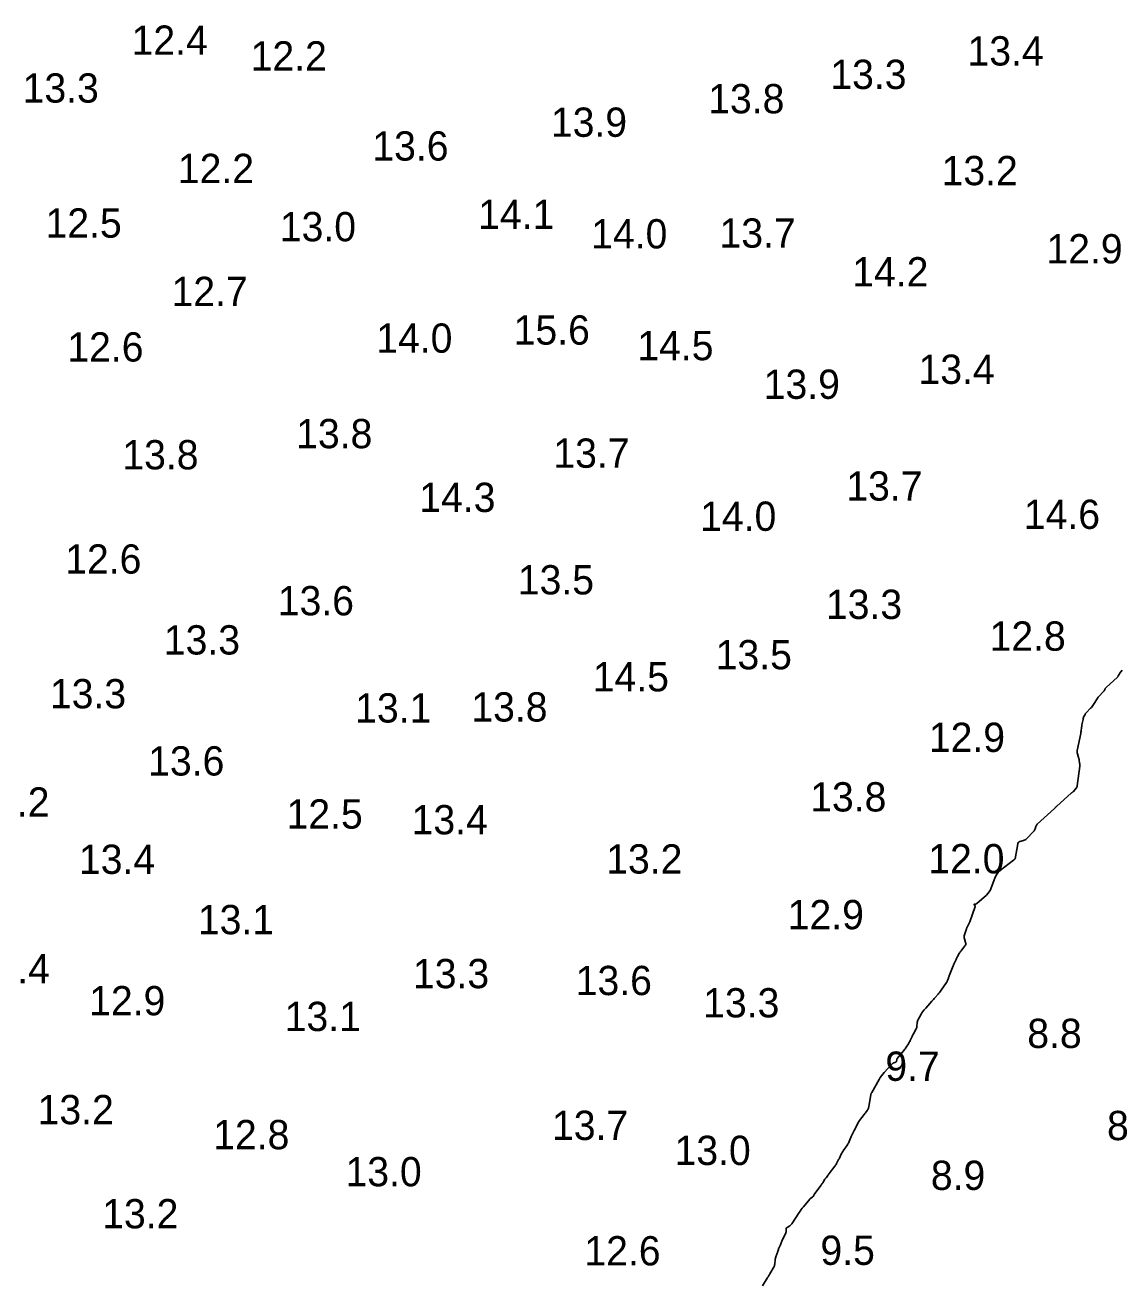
# Model space of a CAD drawing. Extents: x 815352 to 820877, y 582403 to 597439.
# Drawn here: x 820269.3 to 820456.5, y 589266 to 589480.1 of the extents above; entities that cross this region are included whole.
import ezdxf

# ---------------------------------------------------------------- set-up
doc = ezdxf.new("R2010")
doc.units = 0
doc.layers.add('V-CONT-EL12', color=7, linetype='Continuous')
doc.layers.add('V-TOPO-SOUN', color=7, linetype='Continuous')

msp = doc.modelspace()

# ---------------------------------------------------------------- linework, layer by layer
at = {"layer": 'V-CONT-EL12'}
msp.add_lwpolyline([(820395.26, 589264.81), (820396.07, 589266.1), (820396.11, 589266.16), (820396.15, 589266.22), (820396.19, 589266.29), (820396.23, 589266.35), (820396.39, 589266.6), (820396.43, 589266.66), (820396.47, 589266.73), (820396.51, 589266.79), (820396.54, 589266.86), (820397.25, 589268.13), (820397.31, 589268.25), (820397.35, 589268.38), (820397.38, 589268.51), (820397.4, 589268.65), (820397.45, 589269.2), (820397.47, 589269.34), (820397.49, 589269.47), (820397.52, 589269.6), (820397.56, 589269.74), (820397.88, 589270.66), (820397.93, 589270.81), (820397.99, 589270.96), (820398.04, 589271.11), (820398.1, 589271.25), (820398.33, 589271.84), (820398.39, 589271.98), (820398.45, 589272.13), (820398.51, 589272.27), (820398.58, 589272.42), (820399.26, 589273.87), (820399.29, 589273.94), (820399.32, 589274.03), (820399.33, 589274.11), (820399.33, 589274.2), (820399.33, 589274.54), (820399.34, 589274.62), (820399.37, 589274.69), (820399.42, 589274.75), (820399.48, 589274.8), (820399.94, 589275.07), (820400.03, 589275.14), (820400.12, 589275.21), (820400.2, 589275.3), (820400.27, 589275.39), (820401.53, 589277.32), (820401.7, 589277.58), (820401.88, 589277.83), (820402.07, 589278.07), (820402.26, 589278.31), (820403.34, 589279.63), (820403.39, 589279.68), (820403.44, 589279.73), (820403.49, 589279.77), (820403.55, 589279.81), (820403.83, 589279.97), (820403.86, 589280), (820403.89, 589280.03), (820403.92, 589280.06), (820403.94, 589280.09), (820404.03, 589280.25), (820404.05, 589280.29), (820404.07, 589280.32), (820404.1, 589280.36), (820404.12, 589280.39), (820405.23, 589281.94), (820405.32, 589282.06), (820405.4, 589282.18), (820405.49, 589282.31), (820405.57, 589282.43), (820405.95, 589283), (820406.01, 589283.09), (820406.07, 589283.17), (820406.13, 589283.26), (820406.19, 589283.34), (820406.43, 589283.66), (820406.49, 589283.75), (820406.55, 589283.83), (820406.61, 589283.91), (820406.67, 589283.99), (820407.62, 589285.22), (820407.71, 589285.33), (820407.78, 589285.44), (820407.85, 589285.56), (820407.92, 589285.68), (820408.17, 589286.15), (820408.23, 589286.27), (820408.29, 589286.4), (820408.36, 589286.52), (820408.42, 589286.64), (820408.74, 589287.3), (820408.82, 589287.45), (820408.9, 589287.59), (820408.99, 589287.73), (820409.08, 589287.87), (820409.8, 589288.91), (820409.88, 589289.04), (820409.96, 589289.17), (820410.03, 589289.3), (820410.09, 589289.44), (820410.31, 589290.01), (820410.37, 589290.15), (820410.43, 589290.29), (820410.49, 589290.42), (820410.56, 589290.56), (820410.87, 589291.2), (820410.95, 589291.35), (820411.03, 589291.5), (820411.1, 589291.65), (820411.18, 589291.8), (820411.5, 589292.43), (820411.58, 589292.59), (820411.67, 589292.74), (820411.76, 589292.88), (820411.86, 589293.02), (820412.65, 589294.06), (820412.71, 589294.14), (820412.77, 589294.22), (820412.83, 589294.29), (820412.88, 589294.37), (820413.15, 589294.74), (820413.18, 589294.79), (820413.21, 589294.84), (820413.24, 589294.89), (820413.27, 589294.94), (820413.37, 589295.16), (820413.4, 589295.22), (820413.41, 589295.27), (820413.43, 589295.33), (820413.44, 589295.39), (820413.76, 589297.49), (820413.76, 589297.53), (820413.77, 589297.56), (820413.79, 589297.59), (820413.81, 589297.61), (820413.88, 589297.73), (820413.9, 589297.75), (820413.92, 589297.78), (820413.94, 589297.81), (820413.96, 589297.84), (820415.21, 589300.07), (820415.4, 589300.38), (820415.6, 589300.69), (820415.83, 589300.97), (820416.07, 589301.25), (820417.47, 589302.76), (820417.52, 589302.81), (820417.58, 589302.85), (820417.64, 589302.88), (820417.71, 589302.91), (820418.03, 589303), (820418.08, 589303.02), (820418.12, 589303.05), (820418.15, 589303.1), (820418.17, 589303.15), (820418.21, 589303.4), (820418.22, 589303.46), (820418.24, 589303.52), (820418.27, 589303.57), (820418.3, 589303.62), (820419.44, 589305.03), (820419.55, 589305.16), (820419.65, 589305.3), (820419.74, 589305.43), (820419.83, 589305.57), (820420.2, 589306.15), (820420.28, 589306.28), (820420.36, 589306.42), (820420.44, 589306.56), (820420.51, 589306.7), (820420.77, 589307.27), (820420.84, 589307.41), (820420.91, 589307.56), (820420.98, 589307.7), (820421.06, 589307.84), (820421.54, 589308.73), (820421.59, 589308.84), (820421.63, 589308.95), (820421.65, 589309.07), (820421.67, 589309.19), (820421.69, 589309.69), (820421.7, 589309.81), (820421.73, 589309.93), (820421.77, 589310.05), (820421.82, 589310.16), (820422.4, 589311.22), (820422.45, 589311.31), (820422.51, 589311.41), (820422.57, 589311.5), (820422.64, 589311.58), (820422.91, 589311.92), (820422.98, 589312), (820423.05, 589312.09), (820423.13, 589312.17), (820423.2, 589312.25), (820424.22, 589313.41), (820424.36, 589313.57), (820424.49, 589313.72), (820424.63, 589313.88), (820424.76, 589314.03), (820425.29, 589314.65), (820425.42, 589314.81), (820425.55, 589314.97), (820425.67, 589315.13), (820425.79, 589315.3), (820426.69, 589316.61), (820426.75, 589316.7), (820426.8, 589316.79), (820426.85, 589316.88), (820426.89, 589316.98), (820427.04, 589317.37), (820427.08, 589317.46), (820427.12, 589317.56), (820427.15, 589317.66), (820427.19, 589317.75), (820427.84, 589319.44), (820427.9, 589319.58), (820427.96, 589319.72), (820428.02, 589319.86), (820428.08, 589320), (820428.35, 589320.56), (820428.41, 589320.69), (820428.47, 589320.81), (820428.53, 589320.94), (820428.6, 589321.06), (820428.88, 589321.55), (820428.95, 589321.67), (820429.02, 589321.79), (820429.1, 589321.9), (820429.19, 589322.01), (820429.87, 589322.86), (820429.95, 589322.99), (820430, 589323.14), (820430.01, 589323.29), (820429.98, 589323.44), (820429.77, 589324.09), (820429.74, 589324.25), (820429.72, 589324.42), (820429.74, 589324.58), (820429.78, 589324.74), (820430.06, 589325.62), (820430.1, 589325.74), (820430.14, 589325.85), (820430.19, 589325.96), (820430.25, 589326.07), (820430.47, 589326.51), (820430.53, 589326.62), (820430.58, 589326.73), (820430.62, 589326.85), (820430.67, 589326.96), (820431.58, 589329.61), (820431.59, 589329.65), (820431.59, 589329.69), (820431.58, 589329.73), (820431.55, 589329.76), (820431.44, 589329.91), (820431.42, 589329.94), (820431.42, 589329.96), (820431.43, 589329.98), (820431.47, 589329.99), (820431.69, 589330), (820431.75, 589330.01), (820431.79, 589330.03), (820431.84, 589330.05), (820431.88, 589330.08), (820433.52, 589331.54), (820433.78, 589331.8), (820434.01, 589332.1), (820434.2, 589332.42), (820434.35, 589332.76), (820434.97, 589334.46), (820435.14, 589334.84), (820435.36, 589335.19), (820435.62, 589335.5), (820435.94, 589335.78), (820438.16, 589337.5), (820438.19, 589337.52), (820438.21, 589337.54), (820438.24, 589337.56), (820438.26, 589337.58), (820438.36, 589337.66), (820438.38, 589337.68), (820438.4, 589337.71), (820438.41, 589337.73), (820438.42, 589337.76), (820438.88, 589340.3), (820438.92, 589340.44), (820439, 589340.55), (820439.1, 589340.63), (820439.24, 589340.69), (820439.85, 589340.85), (820439.99, 589340.9), (820440.13, 589340.97), (820440.25, 589341.05), (820440.37, 589341.16), (820441.6, 589342.45), (820441.67, 589342.53), (820441.73, 589342.63), (820441.79, 589342.73), (820441.83, 589342.83), (820441.97, 589343.27), (820442.02, 589343.38), (820442.07, 589343.48), (820442.14, 589343.57), (820442.22, 589343.65), (820445.17, 589346.34), (820445.19, 589346.36), (820445.21, 589346.38), (820445.23, 589346.4), (820445.25, 589346.42), (820445.33, 589346.53), (820445.34, 589346.54), (820445.35, 589346.55), (820445.37, 589346.56), (820445.38, 589346.58), (820445.43, 589346.63), (820445.44, 589346.64), (820445.46, 589346.65), (820445.47, 589346.66), (820445.48, 589346.67), (820448.08, 589348.98), (820448.1, 589349), (820448.13, 589349.03), (820448.16, 589349.05), (820448.19, 589349.07), (820448.3, 589349.15), (820448.33, 589349.17), (820448.35, 589349.2), (820448.38, 589349.22), (820448.4, 589349.25), (820448.85, 589349.78), (820448.92, 589349.88), (820448.98, 589349.99), (820449.02, 589350.11), (820449.05, 589350.23), (820449.46, 589353.54), (820449.47, 589353.67), (820449.47, 589353.79), (820449.46, 589353.92), (820449.45, 589354.05), (820449.38, 589354.56), (820449.36, 589354.68), (820449.33, 589354.81), (820449.3, 589354.93), (820449.26, 589355.06), (820449.07, 589355.67), (820449.03, 589355.82), (820449.02, 589355.96), (820449.02, 589356.11), (820449.04, 589356.25), (820449.64, 589359.15), (820449.66, 589359.27), (820449.68, 589359.39), (820449.7, 589359.51), (820449.71, 589359.63), (820449.77, 589360.12), (820449.79, 589360.24), (820449.8, 589360.36), (820449.83, 589360.48), (820449.85, 589360.6), (820450.04, 589361.54), (820450.05, 589361.59), (820450.06, 589361.63), (820450.06, 589361.67), (820450.07, 589361.71), (820450.1, 589361.87), (820450.11, 589361.91), (820450.12, 589361.95), (820450.14, 589361.99), (820450.15, 589362.03), (820450.37, 589362.41), (820450.42, 589362.49), (820450.47, 589362.56), (820450.52, 589362.63), (820450.58, 589362.69), (820451.32, 589363.45), (820451.46, 589363.6), (820451.59, 589363.76), (820451.71, 589363.92), (820451.83, 589364.09), (820452.44, 589365.04), (820452.53, 589365.18), (820452.63, 589365.32), (820452.73, 589365.44), (820452.84, 589365.57), (820453.41, 589366.18), (820453.47, 589366.24), (820453.52, 589366.31), (820453.57, 589366.38), (820453.62, 589366.45), (820453.79, 589366.74), (820453.83, 589366.81), (820453.88, 589366.88), (820453.94, 589366.94), (820454, 589367), (820455.92, 589368.78), (820455.96, 589368.82), (820456, 589368.86), (820456.03, 589368.91), (820456.06, 589368.96), (820456.21, 589369.24), (820456.21, 589369.25), (820456.22, 589369.27), (820456.23, 589369.28), (820456.23, 589369.29), (820456.25, 589369.34), (820456.25, 589369.35), (820456.26, 589369.36), (820456.27, 589369.37), (820456.28, 589369.38), (820456.74, 589369.97)], dxfattribs=at)

# ---------------------------------------------------------------- texts
at = {"layer": 'V-TOPO-SOUN'}
for s, p in [('12.4 ', (820287.52, 589475.05)), ('13.4 ', (820430.3, 589473.22)), ('12.2 ', (820307.86, 589472.36)), ('13.3 ', (820406.87, 589469.21)), ('13.3 ', (820268.91, 589466.88)), ('13.8 ', (820386.01, 589465.05)), ('13.9 ', (820359.14, 589461.04)), ('13.6 ', (820328.64, 589456.98)), ('12.2 ', (820295.42, 589453.14)), ('13.2 ', (820425.87, 589452.78)), ('14.1 ', (820346.71, 589445.3)), ('12.5 ', (820272.82, 589443.82)), ('13.0 ', (820312.84, 589443.2)), ('14.0 ', (820366.02, 589441.98)), ('13.7 ', (820387.94, 589442.11)), ('12.9 ', (820443.78, 589439.42)), ('14.2 ', (820410.61, 589435.49)), ('12.7 ', (820294.34, 589432.14)), ('15.6 ', (820352.78, 589425.55)), ('14.0 ', (820329.31, 589424.17)), ('12.6 ', (820276.54, 589422.66)), ('14.5 ', (820373.9, 589422.89)), ('13.4 ', (820421.93, 589418.85)), ('13.9 ', (820395.49, 589416.29)), ('13.8 ', (820315.63, 589407.86)), ('13.8 ', (820285.94, 589404.25)), ('13.7 ', (820359.56, 589404.52)), ('13.7 ', (820409.6, 589398.91)), ('14.3 ', (820336.66, 589396.97)), ('14.0 ', (820384.63, 589393.75)), ('14.6 ', (820439.92, 589394.08)), ('12.6 ', (820276.18, 589386.44)), ('13.5 ', (820353.49, 589382.89)), ('13.6 ', (820312.49, 589379.32)), ('13.3 ', (820406.12, 589378.7)), ('13.3 ', (820293.03, 589372.63)), ('12.8 ', (820434.07, 589373.28)), ('13.5 ', (820387.29, 589370.1)), ('14.5 ', (820366.29, 589366.33)), ('13.3 ', (820273.57, 589363.44)), ('13.8 ', (820345.55, 589361.18)), ('13.1 ', (820325.71, 589361.01)), ('12.9 ', (820423.7, 589355.99)), ('13.6 ', (820290.35, 589351.96)), ('13.2 ', (820260.48, 589344.94)), ('13.8 ', (820403.43, 589345.82)), ('12.5 ', (820313.99, 589342.9)), ('13.4 ', (820335.35, 589341.92)), ('13.4 ', (820278.53, 589335.16)), ('13.2 ', (820368.59, 589335.22)), ('12.0 ', (820423.6, 589335.26)), ('13.1 ', (820298.84, 589324.86)), ('12.9 ', (820399.59, 589325.71)), ('13.4 ', (820260.55, 589316.46)), ('13.3 ', (820335.58, 589315.64)), ('13.6 ', (820363.38, 589314.46)), ('12.9 ', (820280.27, 589311.01)), ('13.3 ', (820385.15, 589310.65)), ('13.1 ', (820313.67, 589308.32)), ('8.8', (820440.51, 589305.43)), ('9.7', (820416.27, 589299.82)), ('13.2 ', (820271.47, 589292.41)), ('13.7 ', (820359.33, 589289.72)), ('8.0', (820454.13, 589289.69)), ('12.8 ', (820301.46, 589288.14)), ('13.0 ', (820380.26, 589285.45)), ('13.0 ', (820324.06, 589281.81)), ('8.9', (820424.04, 589281.19)), ('13.2 ', (820282.5, 589274.63)), ('12.6 ', (820364.86, 589268.3)), ('9.5', (820405.18, 589268.39))]:
    msp.add_text(s, height=5, dxfattribs=at).set_placement(p)

doc.saveas('drawing.dxf')
